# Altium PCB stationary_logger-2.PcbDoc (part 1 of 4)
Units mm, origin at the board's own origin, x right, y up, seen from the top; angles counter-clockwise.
Board outline 105 x 45 mm, 4 copper layers (Top Layer, Layer 2, Layer 3, Bottom Layer), stack 1.492 mm thick; 317 components, 187 nets, 816 pads, 302 vias.
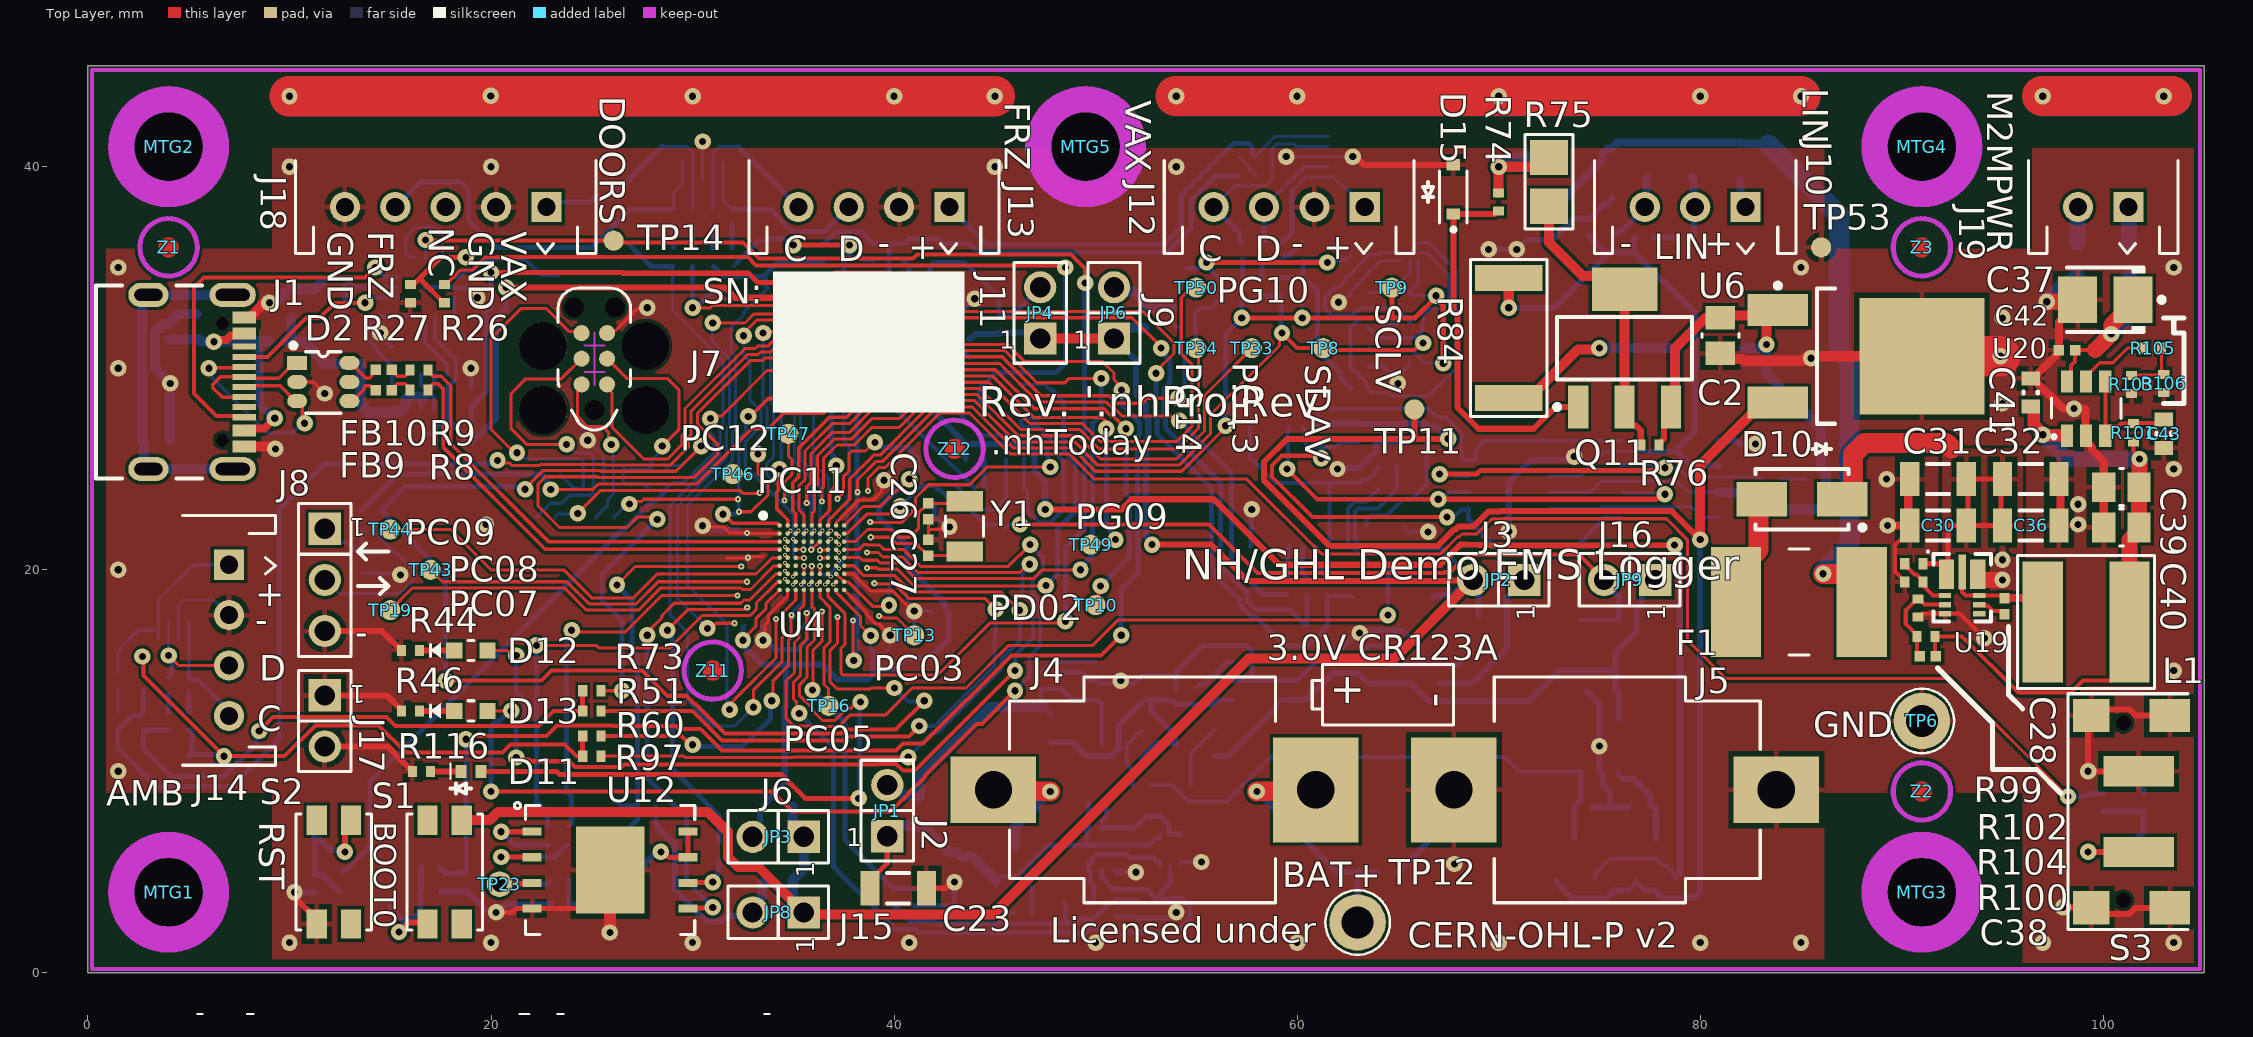
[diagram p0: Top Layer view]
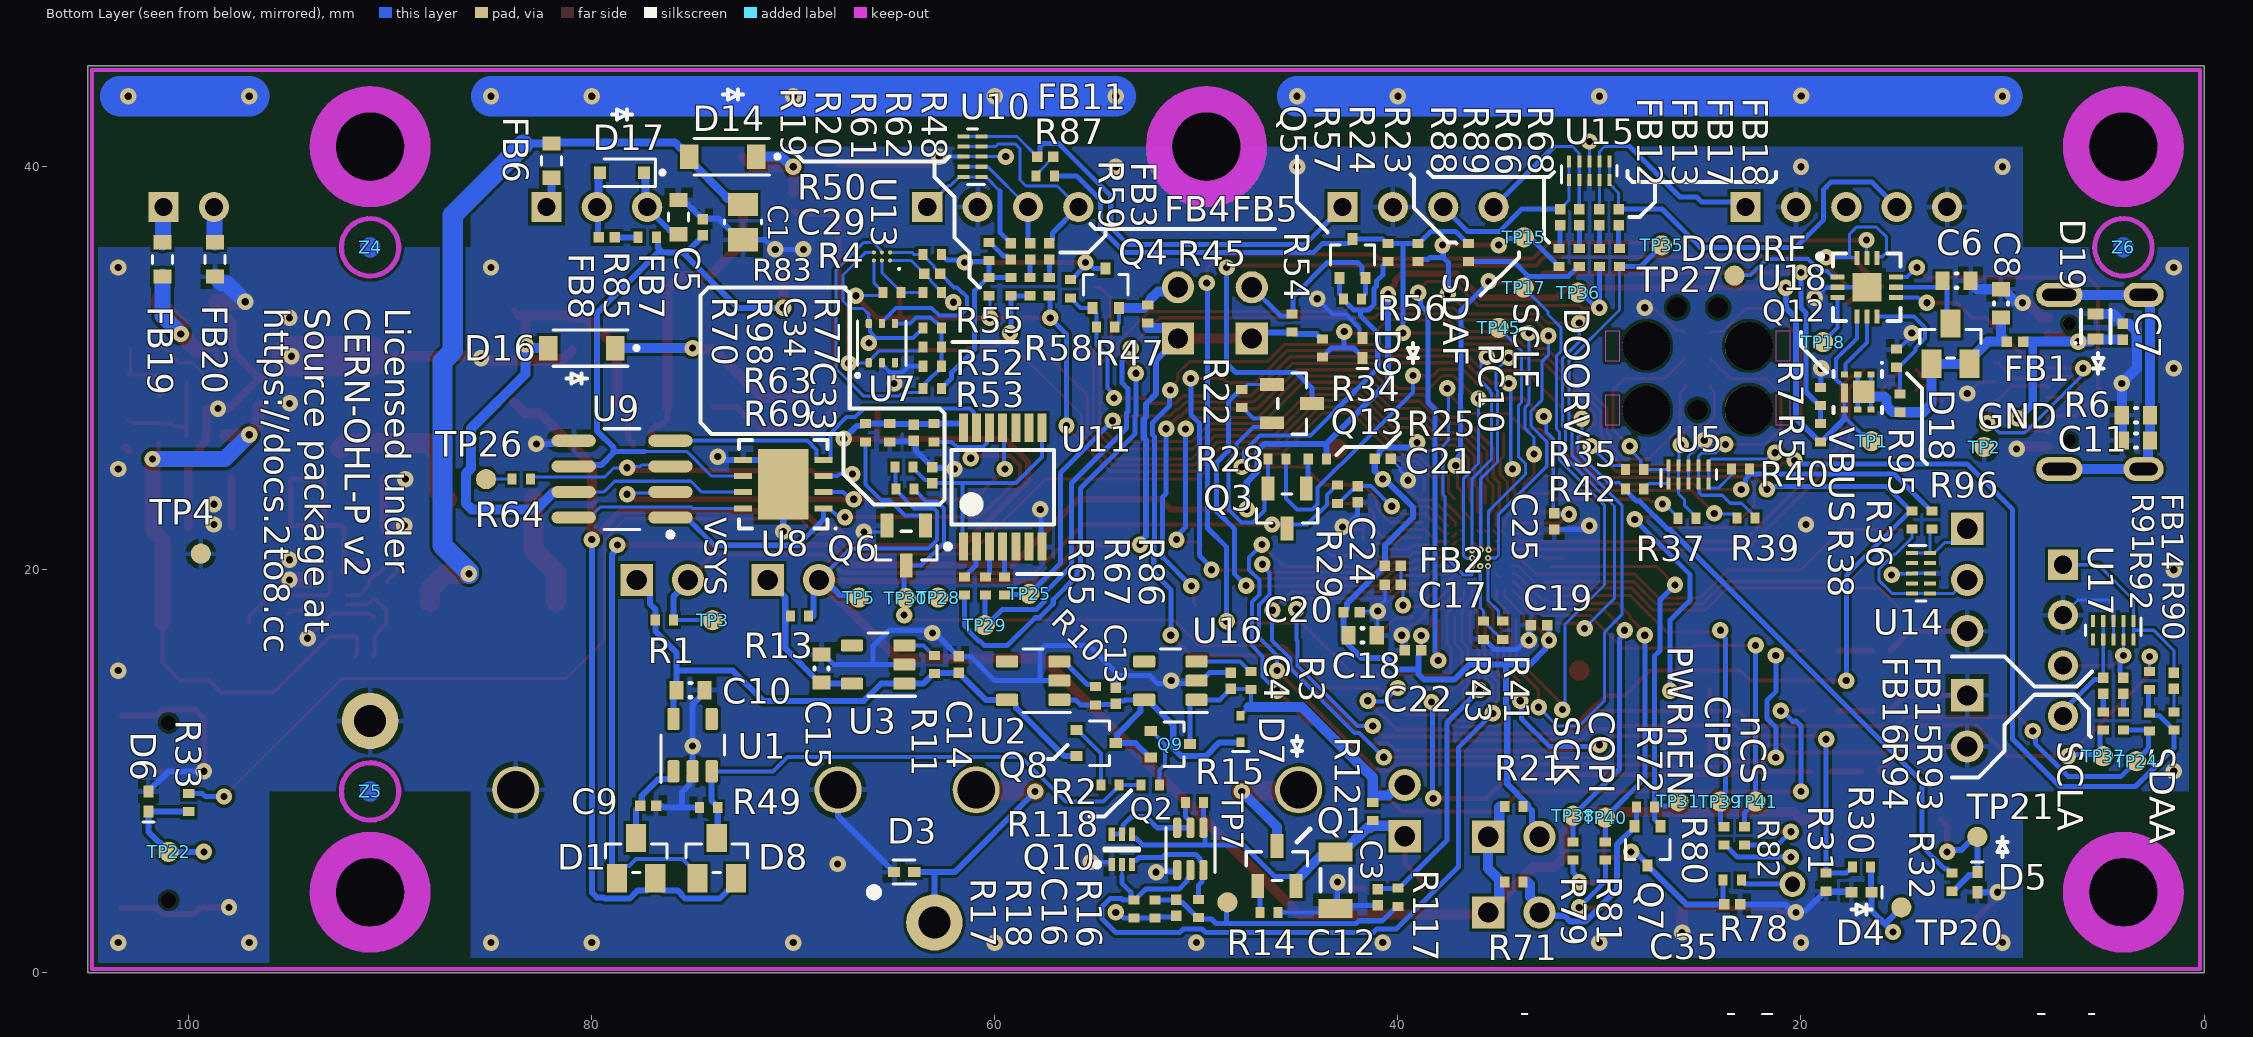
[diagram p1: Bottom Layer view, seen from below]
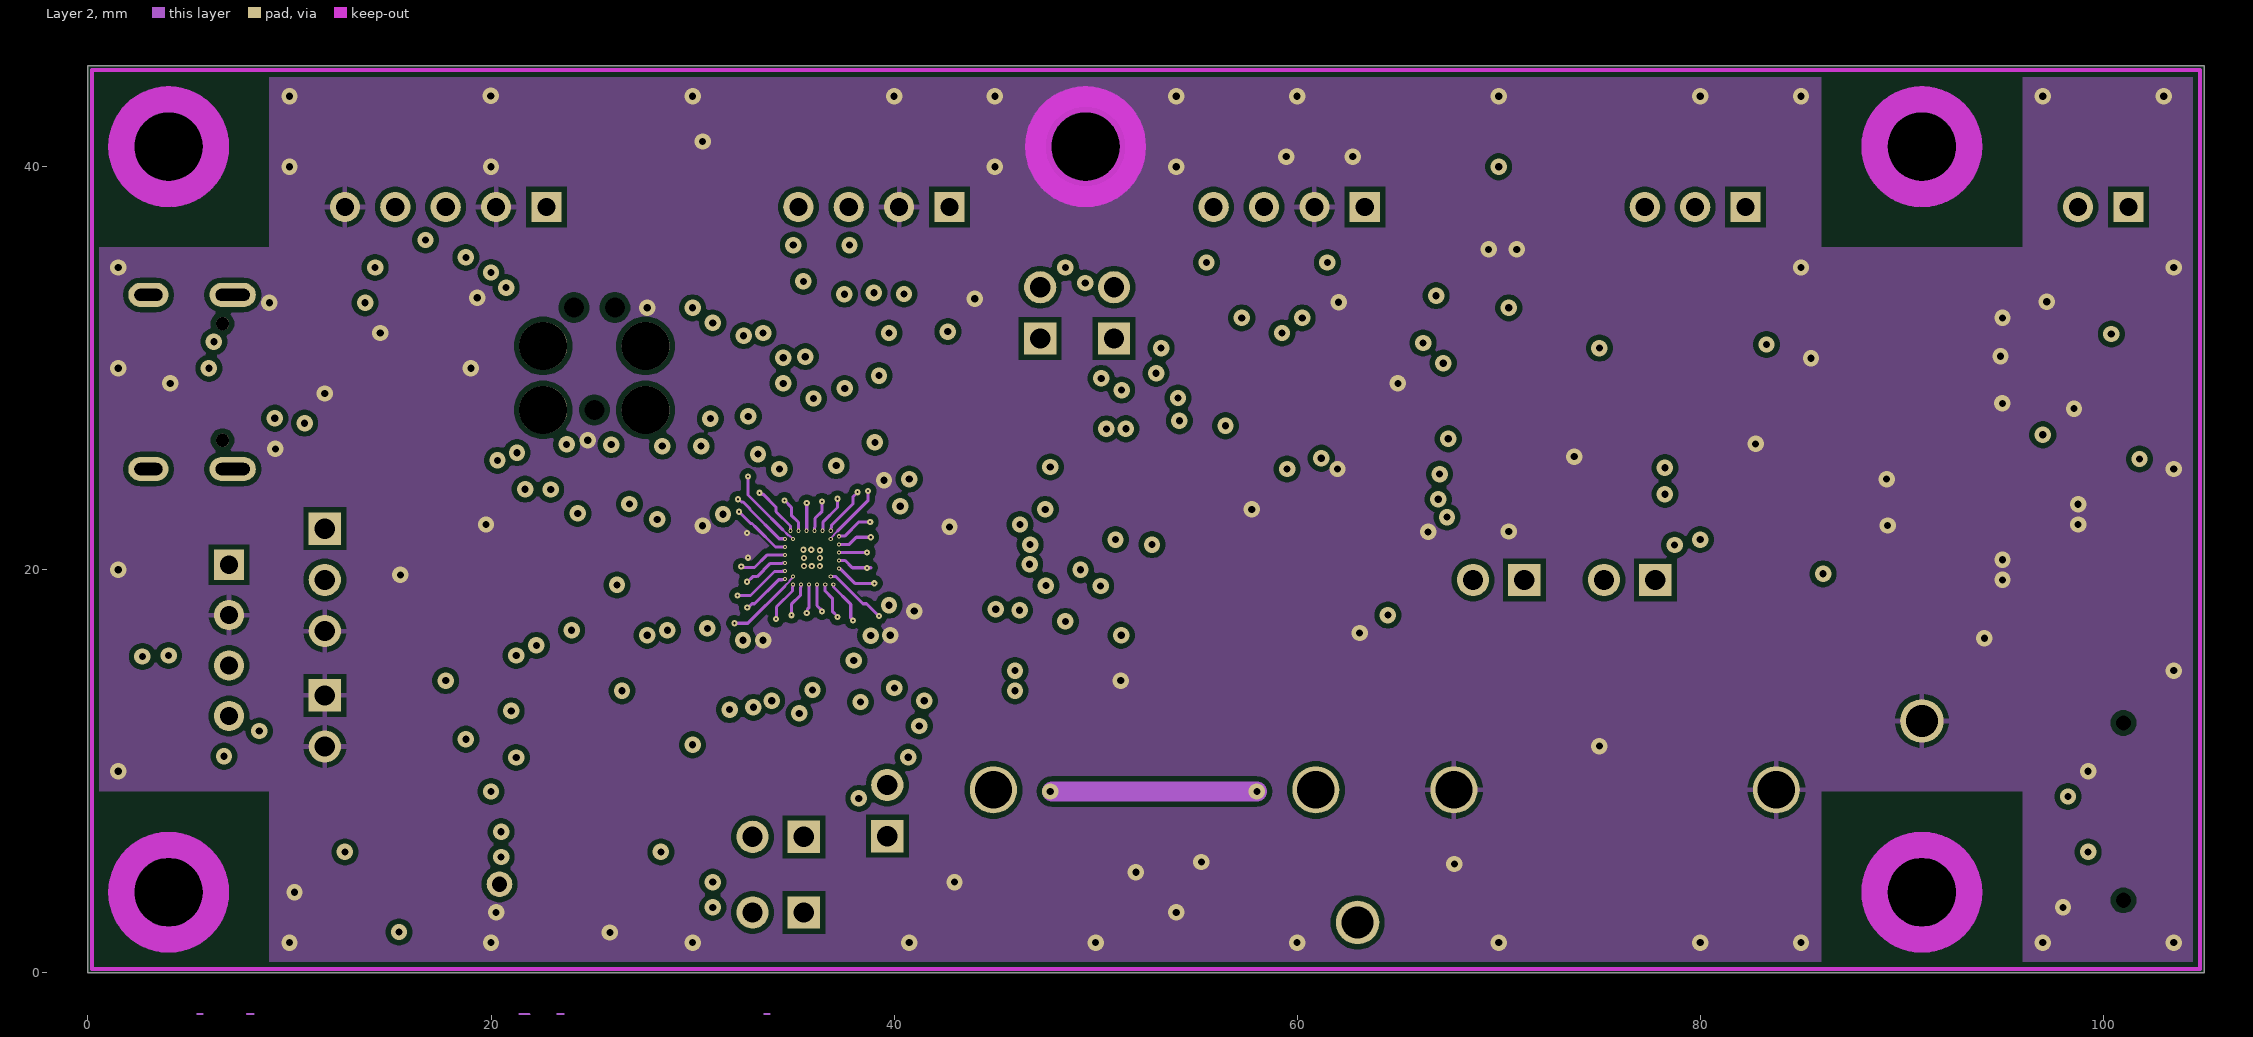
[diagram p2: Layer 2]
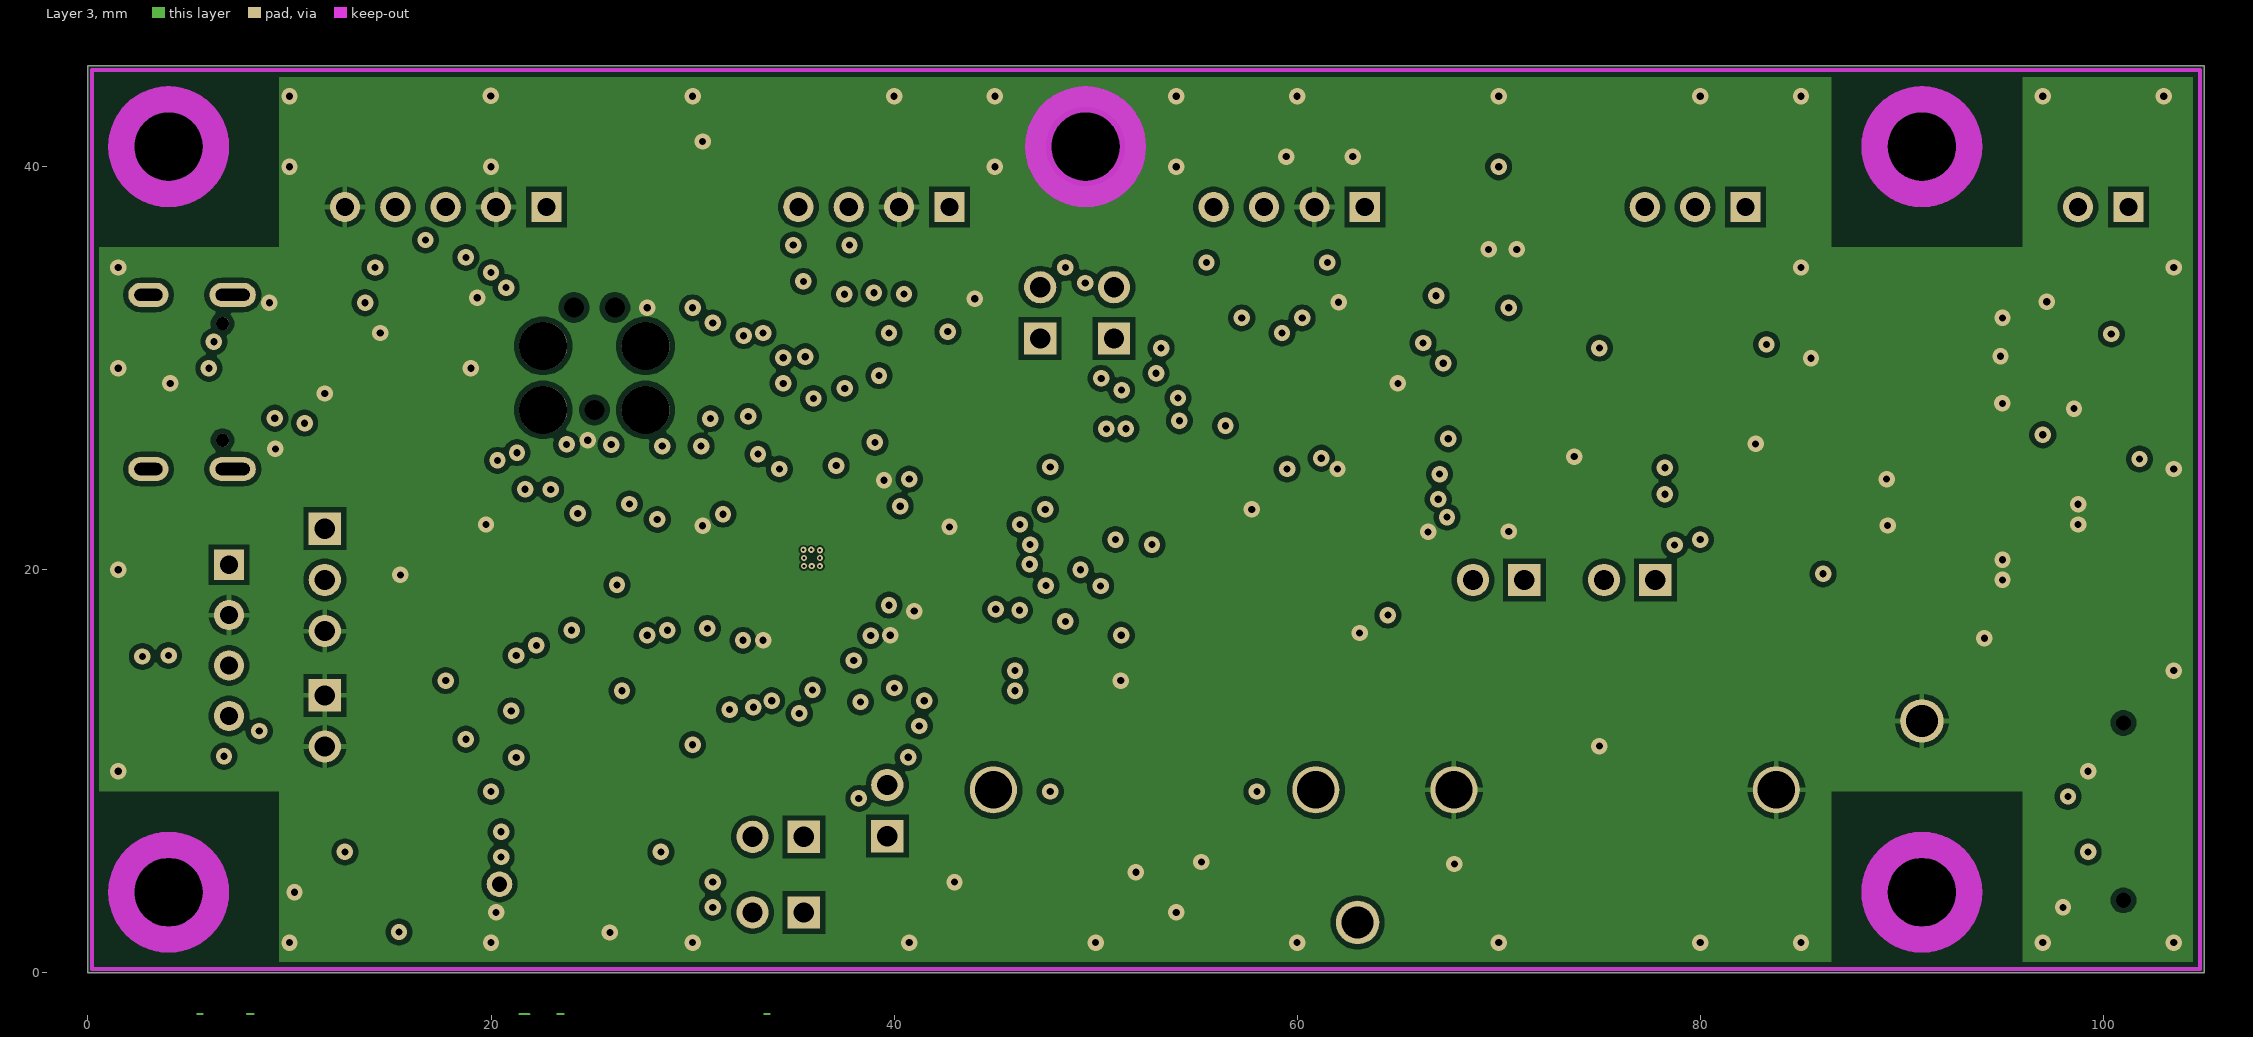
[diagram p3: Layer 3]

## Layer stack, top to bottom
Top Solder: solder mask 0.0356, Solder Resist, Dk 3.9
Top Layer: signal copper 0.0178
Dielectric 2: prepreg 0.0965, PP-006, Dk 3.9
Layer 2: signal copper 0.035
Dielectric 1: dielectric 1.1938, FR-4, Dk 3.9
Layer 3: signal copper 0.035
Dielectric 3: prepreg 0.0965, PP-006, Dk 3.9
Bottom Layer: signal copper 0.0178
Bottom Solder: solder mask 0.0356, Solder Resist, Dk 3.9

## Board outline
0,0 105,0 105,45 0,45

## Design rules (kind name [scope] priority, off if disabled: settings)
BoardOutlineClearance [All] p1: gap=0.254 ignorepadtopadclearanceinfootprint=FALSE except(0: Arc-SplitContinuation Track-SplitContinuation SMDPad-SplitContinuation THPad-SplitContinuation Via-SplitContinuation Fill-SplitContinuation Poly-SplitContinuation Region-SplitContinuation Text-SplitContinuation)
Clearance Clearance_Fanout [WithinRoom('FanoutRoom')] p1: gap=0.083 ignorepadtopadclearanceinfootprint=FALSE
Clearance Clearance_Inner [(OnLayer('Layer 2') OR OnLayer('Layer 3'))] p2: gap=0.254 ignorepadtopadclearanceinfootprint=FALSE
Clearance Clearance_Diff [(InDifferentialPairClass('All Differential Pairs'))] p3: gap=0.178 ignorepadtopadclearanceinfootprint=FALSE
Clearance [All] p4: gap=0.15 ignorepadtopadclearanceinfootprint=FALSE
ComponentClearance [All] p1: gap=0.1 collisioncheckmode=3 verticalgap=0.254 showdistances=FALSE
DiffPairsRouting [All] p1: maxlimit=0.203 minlimit=0.127 mostfreqgap=0.203 toplayer_mingap=0.203 toplayer_minwidth=0.178 toplayer_maxwidth=0.178 toplayer_prefwidth=0.178 midlayer1_maxgap=0.127 midlayer1_prefgap=0.127 midlayer1_minwidth=0.079 midlayer1_maxwidth=0.079 midlayer1_prefwidth=0.079 midlayer2_maxgap=0.127 midlayer2_prefgap=0.127 midlayer2_minwidth=0.079 midlayer2_maxwidth=0.079 midlayer2_prefwidth=0.079 bottomlayer_mingap=0.203 bottomlayer_minwidth=0.178 bottomlayer_maxwidth=0.178 bottomlayer_prefwidth=0.178 impedanceprofiledriven=TRUE impedanceprofileid={696D8CDD-15F8-4D84-82CF-D98015F80A4A} impedanceprofilevalue=90.000000 maxuncoupledlength=12.7
HoleSize HoleSize_microvia [IsMicroVia] p1: absolutevalues=TRUE maxlimit=0.3 minlimit=0.101 maxpercent=80.000 minpercent=20.000
HoleSize HoleSize_fanout [WithinRoom('FanoutRoom')] p2: absolutevalues=TRUE maxlimit=2 minlimit=0.12 maxpercent=80.000 minpercent=20.000
HoleSize [All] p3: absolutevalues=TRUE maxlimit=6.35 minlimit=0.152 maxpercent=80.000 minpercent=20.000
MatchedLengths DiffMatchedLengths [InDifferentialPair('No Differential Pair')] p1: tolerance=1.092 checknetsindiffpair=TRUE checkdiffpairvsdiffpair=FALSE checkxsignals=FALSE checkothers=FALSE
MinimumAnnularRing MinimumAnnularRing_MicroFanout [IsMicroVia AND WithinRoom('FanoutRoom')] p1: minimumring=0.05
MinimumAnnularRing MinimumAnnularRing_Fanout [WithinRoom('FanoutRoom')] p2: minimumring=0.087
MinimumAnnularRing MinimumAnnularRing_MicroVia [IsMicroVia] p3: minimumring=0.101
MinimumAnnularRing MinimumAnnularRing_Inner [(OnLayer('Layer 2') OR OnLayer('Layer 3'))] p4: minimumring=0.229
MinimumAnnularRing [All] p5: minimumring=0.203
MinimumSolderMaskSliver [All] p1: minsoldermaskwidth=0.102
PlaneClearance [All] p1: clearance=0.254
PolygonConnect [All] p1: thpad.connectstyle=Relief thpad.reliefconductorwidth=0.254 thpad.reliefentries=4 thpad.polygonreliefangle="90 Angle" thpad.airgapwidth=0.254 smdpad.connectstyle=Relief smdpad.reliefconductorwidth=0.254 smdpad.reliefentries=4 smdpad.polygonreliefangle="90 Angle" smdpad.airgapwidth=0.254 via.connectstyle=Direct via.reliefconductorwidth=0.254 via.reliefentries=4 via.polygonreliefangle="90 Angle" via.airgapwidth=0.254
RoomDefinition FanoutRoom [InComponentClass('FanoutClass')] p1: confinementstyle=ConfineIn formatcopy=TRUE lockcomponents=FALSE outline 33.159,18.314 38.5,18.314 38.5,23.14 33.159,23.14
RoutingVias RoutingMicroVias [IsMicroVia] p1: holewidth=0.102 width=0.203 viastyle="Through Hole" minholewidth=0.102 minwidth=0.203 maxholewidth=0.102 maxwidth=0.305
RoutingVias RoutingVias_Fanout [WithinRoom('FanoutRoom')] p2: holewidth=0.711 width=1.27 viastyle="Through Hole" minholewidth=0.13 minwidth=0.305 maxholewidth=0.711 maxwidth=1.27
RoutingVias [All] p3: holewidth=0.356 width=0.813 viastyle="Through Hole" minholewidth=0.356 minwidth=0.813 maxholewidth=0.711 maxwidth=1.27
SilkToSilkClearance [All] p1: silktosilkclearance=0.127
SilkToSolderMaskClearance [IsPad] p1: minsilkscreentomaskgap=0.127 clearancetoexposedcopper=TRUE
SolderMaskExpansion [All] p1: expansion=0.049 istentingtop=FALSE
Width Width_Fanout [WithinRoom('FanoutRoom')] p1: maxlimit=2.54 minlimit=0.102 preferedwidth=0.254
Width [All] p2: maxlimit=6.35 minlimit=0.152 preferedwidth=0.254
23 further rules are at their usual default settings.

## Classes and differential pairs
component class FanoutClass: U4
differential pair USB_ESD_D: +USB_ESD_D_P -USB_ESD_D_N
differential pair USB_CONN_D: +USB_CONN_D_P -USB_CONN_D_N
differential pair USB.D: +USB.D_P -USB.D_N
differential pair D: +D_P -D_N

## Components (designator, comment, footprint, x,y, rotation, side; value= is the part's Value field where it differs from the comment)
C1 "50V X7R 0805" CAPC2012X145 72.5,37.25 r270 bottom value=1E-6
C2 "50V X7R 0805" CAPC2012X145 81,31.625 r270 top value=1E-6
C3 "10V X7S 0402" CAPC1005X55,0402,L 41,3.75 r90 bottom value=1E-6
C4 "10V X7R 0402" CAPC1005X55,0402,L 48.291,14.5 r270 bottom value=1E-7
C5 "50V C0G 0402" CAPC1005X55,0402,L 74.5,37 r90 bottom value=1E-10
C6 "50V X7R 0603" CAPC1608X100,0603,L 12.28,34.345 r180 bottom value=1E-7
C7 "50V X7R 0402" CAPC1005X60,0402,L 4.03,31.82 r270 bottom value=1E-8
C8 "16V X7R 0603" CAPC1608X100,0603,L 10.08,33.22 r270 bottom value=4.7E-6
C9 "10V X7S 0402" CAPC1005X55,0402,L 77.2,8.3 r0 bottom value=1E-6
C10 "10V X5R 0603" CAPC1608X100,0603,L 75.1,14.025 r180 bottom value=2.2E-6
C11 "50V X7R 0603" CAPC1608X100,0603,L 3.38,26.42 r0 bottom value=1E-7
C12 "10V 20% 1206" CAPC3216X190,1206,L 43.1,4.6 r90 bottom value=4.7E-5
C13 "10V X7R 0402" CAPC1005X55,0402,L 54,13.75 r270 bottom value=1E-7
C14 "10V X7S 0402" CAPC1005X55,0402,L 61.8,15.3 r270 bottom value=1E-6
C15 "10V X5R 0603" CAPC1608X100,0603,L 68.6,15.1 r90 bottom value=2.2E-6
C16 "10V X7R 0402" CAPC1005X55,0402,L 51,3.225 r90 bottom value=1E-7
C17 "10V X7R 0402" CAPC1005X55,0402,L 40.25,19.25 r0 bottom value=1E-7
C18 "16V X7R 0603" CAPC1608X100,0603,L 41.75,16.75 r0 bottom value=4.7E-6
C19 "10V X7R 0402" CAPC1005X55,0402,L 33,17.25 r180 bottom value=1E-7
C20 "10V X7R 0402" CAPC1005X55,0402,L 42.3,17.89 r0 bottom value=1E-7
C21 "10V X7R 0402" CAPC1005X55,0402,L 40.75,25.5 r0 bottom value=1E-7
C22 "10V X7R 0402" CAPC1005X55,0402,L 39.25,16 r180 bottom value=1E-7
C23 "10V 20% 1206" CAPC3216X190,1206,L 40.2,4.2 r180 top value=4.7E-5
C24 "10V X7R 0402" CAPC1005X55,0402,L 42,23.75 r90 bottom value=1E-7
C25 "10V X7R 0402" CAPC1005X55,0402,L 32.25,22.4 r90 bottom value=1E-7
C26 "50V C0G 0402" CAPC1005X60,0402,L 41.705,22.9 r90 top value=1.5E-11
C27 "50V C0G 0402" CAPC1005X60,0402,L 41.705,21.1 r270 top value=1.5E-11
C28 "10V X7R 0402" CAPC1005X55,0402,L 95.1,18.2 r270 top value=1E-7
C29 "10V X7R 0402" CAPC1005X55,0402,L 63.107,34.7 r180 bottom value=1E-7
C30 "50V X7R 1206" CAPC3216X190,1206,L 91.8,22.2 r0 top value=4.7E-6
C31 "50V X7R 1206" CAPC3216X190,1206,L 91.8,24.5 r0 top value=4.7E-6
C32 "50V X7R 1206" CAPC3216X190,1206,L 96.4,24.5 r180 top value=4.7E-6
C33 "10V X7R 0402" CAPC1005X55,0402,L 63.11,24.7 r270 bottom value=1E-7
C34 "10V X7R 0402" CAPC1005X55,0402,L 64.015,26.8 r90 bottom value=1E-7
C35 "10V X7R 0402" CAPC1005X55,0402,L 23.41,3.4 r0 bottom value=1E-7
C36 "50V X7R 1206" CAPC3216X190,1206,L 96.4,22.2 r180 top value=4.7E-6
C37 "6.3V B 20% 55mO" CAPMP3528X21N[SIZEB] 100.1,33.4 r180 top value=0.0001
C38 "50V C0G 0402" CAPC1005X55,0402,L 91.3,15.7 r180 top value=4.7E-11
C39 "16V X5R 0805" CAPC2012X145 100.9,24.1 r180 top value=2.2E-5
C40 "16V X5R 0805" CAPC2012X145 100.9,22.1 r180 top value=2.2E-5
C41 "50V X7R 0603" CAPC1608X100,0603,L 96.4,28.8 r270 top value=1E-7
C42 "10V X7R 0402" CAPC1005X55,0402,L 98.2,30.9 r0 top value=1E-7
C43 "16V X7R 0603" CAPC1608X100,0603,L 103,26.75 r90 top value=4.7E-6
D1 "BAT54C" SOT23-3B 77.8,5.691 r0 bottom
D2 "TVS" SOT23-6 11.675,29.32 r0 top
D3 "BiTVS 3.6Vw 6.3Vc" TI_2-X1SON 64.5,5 r180 bottom
D4 "TVS 3.6Vw 8.9Vc" TI_2-X1SON_DFN65P100X60-2L 17,4 r0 bottom
D5 "TVS 3.6Vw 8.9Vc" TI_2-X1SON_DFN65P100X60-2L 11.25,4.5 r270 bottom
D6 "TVS 3.6Vw 8.9Vc" TI_2-X1SON_DFN65P100X60-2L 102,8.5 r90 bottom
D7 "30V 200mA" SOD-523_130x90x70 47.8,12.1 r90 bottom
D8 "BAT54C" SOT23-3B 73.8,5.691 r0 bottom
D9 "TVS 3.6Vw 8.9Vc" TI_2-X1SON_DFN65P100X60-2L 41.75,31 r90 bottom
D10 "50V 1A" DO-214AC_DIODES 85.05,23.5 r180 top
D11 "RED" LEDC1005X04NRED,0402, 19,10 r0 top
D12 "GRN" LEDC1608X06NGRN,0603, 19,16 r0 top
D13 "YEL" LEDC1608X06NYEL,0603, 19,13 r0 top
D14 "1N4148" SOD-123 73.5,40.5 r0 bottom
D15 "27V 300mW" SOD-323 67.75,38.877 r90 top
D16 "1N4148" SOD-123 80.5,31 r0 bottom
D17 "PESD1LIN" NEXPERIA_SOD-323_PESD1LIN 78.5,39.7 r0 bottom
D18 "BAT54C" SOT23-3B 12.58,31.22 r0 bottom
D19 "22WVM" DFN105P160X60-2N 5.38,32.075 r90 bottom
F1 "33V 1.1A" FUSC7351X12N,2920, 84.9,18.4 r0 top
FB1 "95 mOhm 1.5A" FER1005X60,0402,L 9.38,31.32 r0 bottom value=220
FB2 "0.65 Ohm 200mA" FER1005X60,0402,L 40.25,20.2 r180 bottom value=600
FB3 "0.49 Ohm 350mA" FER1005X60,0402,L 59.2,35.797 r90 bottom value=1000
FB4 "0.49 Ohm 350mA" FER1005X60,0402,L 58.25,35.797 r90 bottom value=1000
FB5 "0.49 Ohm 350mA" FER1005X60,0402,L 57.3,35.797 r90 bottom value=1000
FB6 "220 Ohm 2A" FER1608X100,0603,L 82,40.3 r270 bottom value=220
FB7 "220 Ohm 2A" FER1608X100,0603,L 75.7,37.5 r270 bottom value=220
FB8 "0.49 Ohm 350mA" FER1005X60,0402,L 79.25,36.5 r0 bottom value=1000
FB9 "0.49 Ohm 350mA" FER1005X60,0402,L 14.68,28.92 r0 top value=1000
FB10 "0.49 Ohm 350mA" FER1005X60,0402,L 14.68,29.92 r0 top value=1000
FB11 "0.49 Ohm 350mA" FER1005X60,0402,L 57.5,40.5 r0 bottom value=1000
FB12 "0.49 Ohm 350mA" FER1005X60,0402,L 31.95,37.5 r90 bottom value=1000
FB13 "0.49 Ohm 350mA" FER1005X60,0402,L 31,37.5 r90 bottom value=1000
FB14 "0.49 Ohm 350mA" FER1005X60,0402,L 1.5,14.5 r90 bottom value=1000
FB15 "0.49 Ohm 350mA" FER1005X60,0402,L 4,14.25 r90 bottom value=1000
FB16 "0.49 Ohm 350mA" FER1005X60,0402,L 5,14.25 r90 bottom value=1000
FB17 "0.49 Ohm 350mA" FER1005X60,0402,L 30,37.5 r90 bottom value=1000
FB18 "0.49 Ohm 350mA" FER1005X60,0402,L 29.05,37.5 r90 bottom value=1000
FB19 "220 Ohm 2A" FER1608X100,0603,L 101.3,35.4 r90 bottom value=220
FB20 "220 Ohm 2A" FER1608X100,0603,L 98.7,35.4 r90 bottom value=220
J1 "USBC_16p_4mnt" GCT_USB4105 3,29.32 r270 top locked
J2 "1x2 0.1in" HDR_2PIN 39.662,8.05 r90 top
J3 "1x2 0.1in" HDR_2PIN 70,19.5 r180 top
J4 "17-19mm dia" KEYSTONE_254 52.929,9.08 r0 top locked
J5 "17-19mm dia" KEYSTONE_254 75.779,9.08 r180 top locked
J6 "1x2 0.1in" HDR_2PIN 34.25,6.75 r180 top
J7 "TC2030" TAG-TC2030-LEGS 25.127,30.473 r90 top
J8 "1x3 0.1in" HDR_3PIN 11.75,19.5 r270 top
J9 "1x2 0.1in" HDR_2PIN 50.912,32.75 r90 top
J10 "JST XH" JST_S3B-XH-A(LF)(SN)_LESS_SILK 79.75,38 r180 top locked
J11 "1x2 0.1in" HDR_2PIN 47.25,32.75 r90 top
J12 "JST XH" JST_S4B-XH-A(LF)(SN)_LESS_SILK 59.607,38 r180 top locked
J13 "JST XH" JST_S4B-XH-A(LF)(SN)_LESS_SILK 39,38 r180 top locked
J14 "JST XH" JST_S4B-XH-A(LF)(SN)_LESS_SILK 7,16.5 r270 top locked
J15 "1x2 0.1in" HDR_2PIN 34.25,3 r180 top
J16 "1x2 0.1in" HDR_2PIN 76.5,19.5 r180 top
J17 "1x2 0.1in" HDR_2PIN 11.75,12.5 r270 top
J18 "JST XH" JST_S5B-XH-A(LF)(SN)_LESS_SILK 17.75,38 r180 top locked
J19 "JST XH" JST_S2B-XH-A(LF)(SN)_LESS_SILK 100,38 r180 top
JP1 "jumper" SULLINS_QPC02SXGN-RC 39.662,8.05 r90 top
JP2 "jumper" SULLINS_QPC02SXGN-RC 70,19.5 r0 top
JP3 "jumper" SULLINS_QPC02SXGN-RC 34.25,6.75 r0 top
JP4 "jumper" SULLINS_QPC02SXGN-RC 47.25,32.75 r90 top
JP6 "jumper" SULLINS_QPC02SXGN-RC 50.912,32.75 r270 top
JP8 "jumper" SULLINS_QPC02SXGN-RC 34.25,3 r0 top
JP9 "jumper" SULLINS_QPC02SXGN-RC 76.5,19.5 r0 top
L1 "3A 31mOhm" INDUCTOR-BOURNS_SRN6045 99.15,17.4 r0 top value=6.8E-6
MTG1 "mounting hole" MOUNT_HOLE_3MM_NOCOPPER 4,4 r0 top locked
MTG2 "mounting hole" MOUNT_HOLE_3MM_NOCOPPER 4,41 r0 top locked
MTG3 "mounting hole" MOUNT_HOLE_3MM_NOCOPPER 91,4 r0 top locked
MTG4 "mounting hole" MOUNT_HOLE_3MM_NOCOPPER 91,41 r0 top locked
MTG5 "mounting hole" MOUNT_HOLE_3MM_NOCOPPER 49.5,41 r0 top locked
Q1 "P-CH 30V 3.8A" SOT23-3#1 46,5.3 r180 bottom
Q2 "DUAL N/P 20V" SOT363 50.3,6.15 r90 bottom
Q3 "3904" SOT23-3#2 45.5,23.043 r270 bottom
Q4 "P-CH 20V 820mA" SOT323_65P200X125x100-GSD 54.5,33.972 r90 bottom
Q5 "P-CH 20V 820mA" SOT323_65P200X125x100-GSD 42.25,35.447 r90 bottom
Q6 "3904" SOT23-3#2 64.398,21.2 r270 bottom
Q7 "P-CH 20V 820mA" SOT323_65P200X125x100-GSD 27.61,6.3 r270 bottom
Q8 "P-CH 20V 820mA" SOT323_65P200X125x100-GSD 54.975,11.4 r180 bottom
Q9 "P-CH 20V 820mA" SOT323_65P200X125x100-GSD 51.291,11.346 r180 bottom
Q10 "DUAL N/P 20V" VISHAY_SOT563F_SOTFL50P160X60-6N 53.7,6.13 r90 bottom
Q11 "N-CH 55V 3.8A" SOT230P700X180-4N_ALPHA 76.25,31 r90 top
Q12 "N-CH 30V" STM_PWRFLAT_SON65P200X80_HS-8N 17.182,28.82 r270 bottom
Q13 "P-CH 30V 3.8A" SOT23-3#1 45.25,28.25 r270 bottom
R1 "1/16W 0402 Jumper" RESC1005X40,0402,L 76.4,17.5 r180 bottom value=0
R2 "1/16W 0402 1%" RESC1005X40,0402,L 54.291,9.316 r180 bottom value=300000
R3 "1/16W 0402 Jumper" RESC1005X40,0402,L 47.291,14.5 r90 bottom value=0
R4 "1/16W 0402 Jumper" RESC1005X40,0402,L 63.107,33.75 r180 bottom value=0
R5 "1/16W 0402 1%" RESC1005X40,0402,L 19.032,26.8 r270 bottom value=68000
R6 "1/10W 0603" RESC1608X60,0603,L 3.38,27.67 r0 bottom value=330
R7 "1/16W 0402 1%" RESC1005X40,0402,L 19.032,28.6 r270 bottom value=33000
R8 "1/16W 0402 Jumper" RESC1005X40,0402,L 16.43,28.92 r180 top value=0
R9 "1/16W 0402 Jumper" RESC1005X40,0402,L 16.43,29.92 r180 top value=0
R10 "1/16W 0402 Jumper" RESC1005X40,0402,L 55,13.75 r90 bottom value=0
R11 "1/16W 0402 Jumper" RESC1005X40,0402,L 63,15.3 r90 bottom value=0
R12 "1/16W 0402 Jumper" RESC1005X40,0402,L 41.25,8 r90 bottom value=0
R13 "1/16W 0402 Jumper" RESC1005X40,0402,L 69.7,17.7 r180 bottom value=0
R14 "1/16W 0402 1%" RESC1005X40,0402,L 46.4,3 r180 bottom value=1000
R15 "1/16W 0402 1%" RESC1005X40,0402,L 50.1,8.45 r0 bottom value=100000
R16 "1/16W 0402 1%" RESC1005X40,0402,L 49.9,3.2 r270 bottom value=8200
R17 "1/16W 0402 1%" RESC1005X40,0402,L 53.1,3.174 r270 bottom value=100000
R18 "1/16W 0402 1%" RESC1005X40,0402,L 52.05,3.174 r270 bottom value=10000
R19 "1/16W 0402 1%" RESC1005X40,0402,L 60.3,34.047 r270 bottom value=2740
R20 "1/16W 0402 1%" RESC1005X40,0402,L 59.2,34.047 r270 bottom value=2740
R21 "1/16W 0402 Jumper" RESC1005X40,0402,L 34.25,8.25 r180 bottom value=0
R22 "1/16W 0402 1%" RESC1005X40,0402,L 47.75,28.5 r90 bottom value=100000
R23 "1/16W 0402 1%" RESC1005X40,0402,L 36.5,35.75 r270 bottom value=4750
R24 "1/16W 0402 1%" RESC1005X40,0402,L 39,35.75 r270 bottom value=4750
R25 "1/16W 0402 1%" RESC1005X40,0402,L 44,25.5 r0 bottom value=1000
R26 "1/16W 0402 Jumper" RESC1005X40,0402,L 17.7,33.7 r90 top value=0
R27 "1/16W 0402 Jumper" RESC1005X40,0402,L 16,33.7 r90 top value=0
R28 "1/16W 0402 Jumper" RESC1005X40,0402,L 46,25.5 r0 bottom value=0
R29 "1/16W 0402 Jumper" RESC1005X40,0402,L 43,23.75 r90 bottom value=0
R30 "1/16W 0402 1%" RESC1005X40,0402,L 17,5.25 r180 bottom value=1000
R31 "1/16W 0402 1%" RESC1005X40,0402,L 18.75,4.5 r270 bottom value=100000
R32 "1/16W 0402 1%" RESC1005X40,0402,L 12.5,4.5 r270 bottom value=1000
R33 "1/16W 0402 1%" RESC1005X40,0402,L 100,8.45 r270 bottom value=1000
R34 "1/16W 0402 Jumper" RESC1005X40,0402,L 43.75,31 r270 bottom value=0
R35 "1/16W 0402 1%" RESC1005X40,0402,L 28.25,24.972 r0 bottom value=47.5
R36 "1/16W 0402 1%" RESC1005X40,0402,L 13.5,22.478 r90 bottom value=47.5
R37 "1/16W 0402 1%" RESC1005X40,0402,L 25.652,22.56 r0 bottom value=47.5
R38 "1/16W 0402 1%" RESC1005X40,0402,L 14.5,22.478 r90 bottom value=47.5
R39 "1/16W 0402 1%" RESC1005X40,0402,L 22.725,22.575 r0 bottom value=47.5
R40 "1/16W 0402 1%" RESC1005X40,0402,L 23,25 r180 bottom value=47.5
R41 "1/16W 0402 1%" RESC1005X40,0402,L 34.8,17 r270 bottom value=10000
R42 "1/16W 0402 1%" RESC1005X40,0402,L 28.25,24 r180 bottom value=47.5
R43 "1/16W 0402 1%" RESC1005X40,0402,L 35.75,17 r270 bottom value=402
R44 "1/16W 0402 1%" RESC1005X40,0402,L 16,16 r0 top value=100
R45 "1/16W 0402 Jumper" RESC1005X40,0402,L 52.412,32.697 r90 bottom value=0
R46 "1/16W 0402 1%" RESC1005X40,0402,L 16,13 r0 top value=100
R47 "1/16W 0402 1%" RESC1005X40,0402,L 54.5,32.046 r0 bottom value=1000000
R48 "1/16W 0402 Jumper" RESC1005X40,0402,L 56.25,33.947 r270 bottom value=0
R49 "1/16W 0402 1%" RESC1005X40,0402,L 74.2,8.2 r0 bottom value=100000
R50 "1/16W 0402 1%" RESC1005X40,0402,L 63.107,35.651 r0 bottom value=100
R51 "1/16W 0402 Jumper" RESC1005X40,0402,L 25,13 r180 top value=0
R52 "1/16W 0402 Jumper" RESC1005X40,0402,L 63.107,30.1 r0 bottom value=0
R53 "1/16W 0402 Jumper" RESC1005X40,0402,L 63.107,29 r180 bottom value=0
R54 "1/16W 0402 Jumper" RESC1005X40,0402,L 45.25,32.25 r90 bottom value=0
R55 "1/16W 0402 Jumper" RESC1005X40,0402,L 63.107,32.001 r0 bottom value=0
R56 "1/16W 0402 1%" RESC1005X40,0402,L 42.25,33.447 r0 bottom value=1000000
R57 "1/16W 0402 Jumper" RESC1005X40,0402,L 40.5,35.75 r270 bottom value=0
R58 "1/16W 0402 Jumper" RESC1005X40,0402,L 63.107,31.05 r0 bottom value=0
R59 "1/16W 0402 1%" RESC1005X40,0402,L 60.3,35.797 r90 bottom value=47.5
R60 "1/16W 0402 Jumper" RESC1005X40,0402,L 25,11.75 r180 top value=0
R61 "1/16W 0402 1%" RESC1005X40,0402,L 58.25,34.047 r90 bottom value=47.5
R62 "1/16W 0402 1%" RESC1005X40,0402,L 57.3,34.047 r90 bottom value=47.5
R63 "1/16W 0402 Jumper" RESC1005X40,0402,L 64.515,25.1 r0 bottom value=0
R64 "1/16W 0402 1%" RESC1005X40,0402,L 83.5,24.5 r0 bottom value=33000
R65 "1/16W 0402 Jumper" RESC1005X40,0402,L 61.515,19.2 r270 bottom value=0
R66 "1/16W 0402 1%" RESC1005X40,0402,L 30,35.5 r90 bottom value=47.5
R67 "1/16W 0402 Jumper" RESC1005X40,0402,L 60.465,19.2 r270 bottom value=0
R68 "1/16W 0402 1%" RESC1005X40,0402,L 29,35.5 r90 bottom value=47.5
R69 "1/16W 0402 1%" RESC1005X40,0402,L 64.465,24 r180 bottom value=100000
R70 "1/16W 0402 1%" RESC1005X40,0402,L 66.419,26.8 r90 bottom value=10000
R71 "1/16W 0402 Jumper" RESC1005X40,0402,L 34.25,4.5 r180 bottom value=0
R72 "1/16W 0402 1%" RESC1005X40,0402,L 27.71,8.225 r180 bottom value=1000000
R73 "1/16W 0402 Jumper" RESC1005X40,0402,L 25,14 r180 top value=0
R74 "1/16W 0402 1%" RESC1005X40,0402,L 70,38.25 r270 top value=100000
R75 "2.5W FUSE" RESC3216X70[1206] 72.5,39.25 r90 top value=10
R76 "1/16W 0402 Jumper" RESC1005X40,0402,L 77.5,26.2 r0 top value=0
R77 "1/16W 0402 1%" RESC1005X40,0402,L 63.015,26.8 r270 bottom value=4750
R78 "1/16W 0402 1%" RESC1005X40,0402,L 23.41,4.6 r0 bottom value=1000000
R79 "1/16W 0402 1%" RESC1005X40,0402,L 31.31,6.05 r270 bottom value=33
R80 "1/16W 0402 1%" RESC1005X40,0402,L 23.81,6.8 r270 bottom value=33
R81 "1/16W 0402 1%" RESC1005X40,0402,L 29.71,6.05 r270 bottom value=33
R82 "1/16W 0402 Jumper" RESC1005X40,0402,L 22.81,6.8 r90 bottom value=0
R83 "1/16W 0402 Jumper" RESC1005X40,0402,L 65.107,33.75 r180 bottom value=0
R84 "1W 2512 1%" RESC6534X70[2512] 70.5,31.5 r90 top value=1000
R85 "1/16W 0402 Jumper" RESC1005X40,0402,L 77.25,36.5 r180 bottom value=0
R86 "1/16W 0402 Jumper" RESC1005X40,0402,L 59.515,19.2 r270 bottom value=0
R87 "1/16W 0402 1%" RESC1005X40,0402,L 57.5,39.55 r0 bottom value=47.5
R88 "1/16W 0402 1%" RESC1005X40,0402,L 32,35.5 r90 bottom value=47.5
R89 "1/16W 0402 1%" RESC1005X40,0402,L 31,35.5 r90 bottom value=47.5
R90 "1/16W 0402 1%" RESC1005X40,0402,L 1.5,12.5 r90 bottom value=47.5
R91 "1/16W 0402 1%" RESC1005X40,0402,L 2.7,14.5 r90 bottom value=4750
R92 "1/16W 0402 1%" RESC1005X40,0402,L 2.702,12.448 r270 bottom value=4750
R93 "1/16W 0402 1%" RESC1005X40,0402,L 4,12.5 r90 bottom value=47.5
R94 "1/16W 0402 1%" RESC1005X40,0402,L 5,12.5 r90 bottom value=47.5
R95 "1/16W 0402 1%" RESC1005X40,0402,L 15.08,28.267 r270 bottom value=10000
R96 "1/16W 0402 1%" RESC1005X40,0402,L 15.25,30.5 r270 bottom value=2740
R97 "1/16W 0402 Jumper" RESC1005X40,0402,L 25,10.75 r180 top value=0
R98 "1/16W 0402 1%" RESC1005X40,0402,L 65.217,26.8 r270 bottom value=100000
R99 "1/16W 0402 1%" RESC1005X40,0402,L 90.6,20.3 r180 top value=100000
R100 "1/10W 0402 1%" RESC1005X40,0402,L 91.2,16.7 r180 top value=178000
R101 "1/16W 0402 1%" RESC1005X40,0402,L 101.5,26.8 r90 top value=1000000
R102 "1/10W 0402 1%" RESC1005X40,0402,L 90.6,19.4 r180 top value=23700
R103 "1/10W 0402 1%" RESC1005X40,0402,L 101.4,29.2 r270 top value=23700
R104 "1/16W 0402 1%" RESC1005X40,0402,L 90.8,18.1 r270 top value=33000
R105 "1/16W 0402 Jumper" RESC1005X40,0402,L 102.45,31 r0 top value=0
R106 "1/16W 0402 1%" RESC1005X40,0402,L 103,29.25 r270 top value=1000000
R116 "1/16W 0402 1%" RESC1005X40,0402,L 16.55,10 r0 top value=100
R117 "1/16W 0402 1%" RESC1005X40,0402,L 40,3.75 r270 bottom value=100
R118 "1/16W 0402 1%" RESC1005X40,0402,L 52.291,9.316 r0 bottom value=300000
S1 "SPST-NO" EVQP2x02W_MIRROR 17.7,5 r90 top
S2 "SPST-NO" EVQP2x02W_MIRROR 12.2,5 r270 top
S3 "SPST-NO" TE_1571300 101,8 r90 top
TP1 "TP SMD 1mm" "TP_SMD_Ø1.0mm NO SILK"#1 16.5,26.382 r90 bottom
TP2 "TP SMD 1mm" "TP_SMD_Ø1.0mm NO SILK"#1 10.907,26.093 r90 bottom
TP3 "TP SMD 1mm" "TP_SMD_Ø1.0mm NO SILK"#1 74,17.5 r90 bottom
TP4 "TP SMD 1mm" "TP_SMD_Ø1.0mm NO SILK"#1 99.4,20.8 r0 bottom
TP5 "TP SMD 1mm" "TP_SMD_Ø1.0mm NO SILK"#1 66.75,18.625 r90 bottom
TP6 "TP BLK" KEYSTONE_5011 91,12.5 r90 top
TP7 "TP SMD 1mm" "TP_SMD_Ø1.0mm NO SILK"#1 48.458,3.5 r90 bottom
TP8 "TP SMD 1mm" "TP_SMD_Ø1.0mm NO SILK"#2 61.3,31.2 r180 top
TP9 "TP SMD 1mm" "TP_SMD_Ø1.0mm NO SILK"#1 64.7,34 r180 top
TP10 "TP SMD 1mm" "TP_SMD_Ø1.0mm NO SILK"#1 50,18.25 r90 top
TP11 "TP SMD 1mm" "TP_SMD_Ø1.0mm NO SILK"#1 65.818,27.956 r180 top
TP12 "TP BLK" KEYSTONE_5011 63,2.5 r0 top
TP13 "TP SMD 1mm" "TP_SMD_Ø1.0mm NO SILK"#1 41,16.75 r90 top
TP14 "TP SMD 1mm" "TP_SMD_Ø1.0mm NO SILK"#1 26.084,36.331 r90 top
TP15 "TP SMD 1mm" "TP_SMD_Ø1.0mm NO SILK"#1 33.75,36.5 r0 bottom
TP16 "TP SMD 1mm" "TP_SMD_Ø1.0mm NO SILK"#1 36.75,13.25 r90 top
TP17 "TP SMD 1mm" "TP_SMD_Ø1.0mm NO SILK"#1 33.75,34 r0 bottom
TP18 "TP SMD 1mm" "TP_SMD_Ø1.0mm NO SILK"#1 18.9,31.3 r90 bottom
TP19 "TP SMD 1mm" "TP_SMD_Ø1.0mm NO SILK"#1 15,18 r90 top
TP20 "TP SMD 1mm" "TP_SMD_Ø1.0mm NO SILK"#1 15.017,3.25 r90 bottom
TP21 "TP SMD 1mm" "TP_SMD_Ø1.0mm NO SILK"#1 11.25,6.75 r90 bottom
TP22 "TP SMD 1mm" "TP_SMD_Ø1.0mm NO SILK"#1 101,6 r90 bottom
TP23 "TP TH  0.78mm" TP_TH078H127P 20.42,4.4 r90 top
TP24 "TP SMD 1mm" "TP_SMD_Ø1.0mm NO SILK"#1 3.358,10.502 r90 bottom
TP25 "TP SMD 1mm" "TP_SMD_Ø1.0mm NO SILK"#1 58.282,18.8 r0 bottom
TP26 "TP SMD 1mm" "TP_SMD_Ø1.0mm NO SILK"#1 85.25,24.5 r0 bottom
TP27 "TP SMD 1mm" "TP_SMD_Ø1.0mm NO SILK"#1 23.3,34.6 r90 bottom
TP28 "TP SMD 1mm" "TP_SMD_Ø1.0mm NO SILK"#1 62.815,18.625 r0 bottom
TP29 "TP SMD 1mm" "TP_SMD_Ø1.0mm NO SILK"#1 60.5,17.25 r0 bottom
TP30 "TP SMD 1mm" "TP_SMD_Ø1.0mm NO SILK"#1 64.415,18.6 r0 bottom
TP31 "TP SMD 1mm" "TP_SMD_Ø1.0mm NO SILK"#1 26.077,8.508 r90 bottom
TP33 "TP SMD 1mm" "TP_SMD_Ø1.0mm NO SILK"#1 57.75,31 r90 top
TP34 "TP SMD 1mm" "TP_SMD_Ø1.0mm NO SILK"#1 55,31 r90 top
TP35 "TP SMD 1mm" "TP_SMD_Ø1.0mm NO SILK"#1 26.9,36.1 r0 bottom
TP36 "TP SMD 1mm" "TP_SMD_Ø1.0mm NO SILK"#1 31.054,33.75 r0 bottom
TP37 "TP SMD 1mm" "TP_SMD_Ø1.0mm NO SILK"#1 5,10.75 r90 bottom
TP38 "TP SMD 1mm" "TP_SMD_Ø1.0mm NO SILK"#1 31.31,7.8 r90 bottom
TP39 "TP SMD 1mm" "TP_SMD_Ø1.0mm NO SILK"#1 24,8.5 r90 bottom
TP40 "TP SMD 1mm" "TP_SMD_Ø1.0mm NO SILK"#1 29.71,7.7 r90 bottom
TP41 "TP SMD 1mm" "TP_SMD_Ø1.0mm NO SILK"#1 22.25,8.5 r90 bottom
TP43 "TP SMD 1mm" "TP_SMD_Ø1.0mm NO SILK"#1 17,20 r90 top
TP44 "TP SMD 1mm" "TP_SMD_Ø1.0mm NO SILK"#1 15,22 r90 top
TP45 "TP SMD 1mm" "TP_SMD_Ø1.0mm NO SILK"#1 35,32 r90 bottom
TP46 "TP SMD 1mm" "TP_SMD_Ø1.0mm NO SILK"#1 32,24.75 r90 top
TP47 "TP SMD 1mm" "TP_SMD_Ø1.0mm NO SILK"#1 34.75,26.75 r90 top
TP49 "TP SMD 1mm" "TP_SMD_Ø1.0mm NO SILK"#1 49.75,21.25 r90 top
TP50 "TP SMD 1mm" "TP_SMD_Ø1.0mm NO SILK"#1 55,34 r90 top
TP53 "TP SMD 1mm" "TP_SMD_Ø1.0mm NO SILK"#1 86,36 r180 top
U1 "3.3V 200mA" TI_SOT-23-5_95P280X145L 75,11.3 r90 bottom
U2 "MAX40203" TI_SOT-23-5_95P280X145L 58.1,14.5 r0 bottom
U3 "1.8V 200mA" TI_SOT-23-5_95P280X145L 65.791,15.3 r0 bottom
U4 "STM32L476JEY6TR" STM_BGA72C40P9X9_441X376X58 35.92,20.6 r0 top locked
U5 "PUSB3FA1Z" NEXPERIA_DFN2510_50p250x100x50-10 25.577,24.722 r90 bottom
U6 "35V 5V 0.5A" ONSEMI_DPAK229P991X238-3N 88.25,30.598 r0 top
U7 "TMP117" TI-TMP117-WSON 65.607,31.25 r90 bottom
U8 "LIN XCV" SON80P400X100_HS-9N_NOVIA 70.5,24.25 r0 bottom
U9 "LIN XCV" SOIC127P600X170-8N 78.5,24.5 r0 bottom
U10 "PUSB3FA1Z" NEXPERIA_DFN2510_50p250x100x50-10 61.107,40.5 r0 bottom
U11 "Logic level translator" TSOP65P640X110-14N 59.61,24.1 r90 bottom
U12 "1Gb SPI" SON127P800X95_HS-9N_no_via 25.91,5.1 r0 top
U13 "AMS_AS621x" AMS_BGA6C40P3X2_150X102X60 65.607,35.55 r0 bottom
U14 "PUSB3FA1Z" NEXPERIA_DFN2510_50p250x100x50-10 14.048,19.828 r180 bottom
U15 "PUSB3FA1Z" NEXPERIA_DFN2510_50p250x100x50-10 30.5,39.8 r90 bottom
U16 "MAX40203" TI_SOT-23-5_95P280X145L 51.291,14.5 r0 bottom
U17 "PUSB3FA1Z" NEXPERIA_DFN2510_50p250x100x50-10 4.5,17 r270 bottom
U18 "STM_TCPP01-M12" QFN50P300X300X100_HS-13N 16.73,34.02 r180 bottom
U19 "DIO-AP6335x" DIO_VDFN3020-13A 93,19.1 r0 top
U20 "TI_TPS2553" SOT_23_6 99.15,28 r90 top
Y1 "20ppm 12.5pF" FC-135 43.5,22.15 r270 top value=32768
Z1 "NOBOM-00010" FIDUCIAL_1_3_KEEPOUT 4,36 r0 top locked
Z2 "NOBOM-00010" FIDUCIAL_1_3_KEEPOUT 91,9 r0 top locked
Z3 "NOBOM-00010" FIDUCIAL_1_3_KEEPOUT 91,36 r0 top locked
Z4 "NOBOM-00010" FIDUCIAL_1_3_KEEPOUT 91,36 r180 bottom locked
Z5 "NOBOM-00010" FIDUCIAL_1_3_KEEPOUT 91,9 r180 bottom locked
Z6 "NOBOM-00010" FIDUCIAL_1_3_KEEPOUT 4,36 r180 bottom locked
Z11 "NOBOM-00010" FIDUCIAL_1_3_KEEPOUT 31,15 r0 top locked
Z12 "NOBOM-00010" FIDUCIAL_1_3_KEEPOUT 43,26 r0 top locked

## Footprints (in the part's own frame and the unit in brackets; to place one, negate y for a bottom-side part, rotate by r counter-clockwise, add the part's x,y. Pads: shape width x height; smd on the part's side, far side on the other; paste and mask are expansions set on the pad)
AMS_BGA6C40P3X2_150X102X60 [mm] "BGA, 6-Leads, Body 1.50x1.02mmx0.60mm, Pitch 0.40mm"
  round 0.2 smd mask+0.049: A1(-0.4,0.2) A2(0,0.2) A3(0.4,0.2) B1(-0.4,-0.2) B2(0,-0.2) B3(0.4,-0.2)
  silkscreen extent -0.9,0.57 -0.8,0.67, body extent -0.75,-0.52 0.75,0.52, height 0.6
CAPC1005X55,0402,L [mm] "Chip Capacitor, Body 1.0x0.5mm, Height 0.55mm, IPC High Density"
  rect 0.52x0.52 smd: 1(-0.4,0) 2(0.4,0)
  body extent -0.55,-0.3 0.55,0.3, height 0.55
CAPC1005X60,0402,L [mm]
  rect 0.52x0.52 smd: 1(-0.4,0) 2(0.4,0)
  body extent -0.55,-0.3 0.55,0.3, height 0.6
CAPC1608X100,0603,L [mm] "Chip Capacitor, Body 1.6x0.8mm, Height 1.0mm, IPC High Density"
  rect 0.7x0.9 smd: 1(-0.7,0) 2(0.7,0)
  silkscreen extent -0.05,-0.35 0.05,0.35, body extent -0.87,-0.47 0.88,0.48, height 1
CAPC2012X145 [mm]
  rect 1.16x1.47 smd: 1(-0.875,0) 2(0.875,0)
  silkscreen extent -0.1,-0.92 0.1,0.92, body extent -1,-0.63 1,0.63, height 1.45
CAPC3216X190,1206,L [mm] "Chip Capacitor, Body 3.2x1.6mm, Height 1.9mm, IPC High Density"
  rect 0.95x1.7 smd: 1(-1.4,0) 2(1.4,0)
  silkscreen extent -0.55,-0.75 0.55,0.75, body extent -1.7,-0.9 1.7,0.9, height 1.9
CAPMP3528X21N[SIZEB] [mm] "Molded Capacitor, 2-Leads, Body 3.50x2.85mm, IPC Medium Density"
  rect 1.95x2.3 smd: +(-1.375,0) -(1.375,0)
  silkscreen extent -2.93,-1.6 1.9,1.6, body extent -1.9,-1.5 1.85,1.5, height 2.1
DFN105P160X60-2N [mm] "DFN, 2-Leads, Body 1.00x1.60mm, Pitch 1.05mm, IPC Medium Density"
  rect 0.55x0.8 smd: A(0.625,0) K(-0.625,0)
  silkscreen extent -0.87,-0.73 0.82,1.05, body extent -0.82,-0.53 0.82,0.53, height 0.61
DIO_VDFN3020-13A [mm] "SON, 9-Leads, Body 3.0x2.0mm, Pitch 0.45mm, IPC Medium Density"
  rect 0.75x1.47 smd: 1(-0.772,0.686) 8(0.772,0.686)
  rect 0.6x0.27 smd mask+0.039: 2(-0.847,-0.375) 3(-0.847,-0.825) 4(-0.847,-1.275) 5(0.847,-1.275) 6(0.847,-0.825) 7(0.847,-0.375)
  rect 0.39x1.73 smd: 9(0,0.79)
  silkscreen extent -1.75,-1.68 1.43,1.85, body extent -1,-1.5 1,1.5, height 0.86
DO-214AC_DIODES [mm] "Molded Diode, 2-Leads, Body 4.30x2.61mm, IPC Medium Density"
  rect 2.5x1.7 smd: A(2,0) K(-2,0)
  silkscreen extent -3.13,-1.5 2.3,1.52, body extent -2.3,-1.46 2.3,1.46, height 2.4
EVQP2x02W_MIRROR [mm] "Panasonic EQVP2 switch with 2.5mm nominal height"
  rect 1.45x1 smd: 1(-2.575,0.85) 2(-2.575,-0.85) 3(2.575,0.85) 4(2.575,-0.85)
  silkscreen extent -2.88,-1.88 2.88,1.88, body extent -2.75,-1.75 2.75,1.75, height 2.5
FC-135 [mm]
  rect 1x1.8 smd: 1(-1.25,0) 2(1.25,0)
  silkscreen extent -0.51,-0.95 0.51,0.94, body extent -1.6,-0.75 1.6,0.75, height 0.81
FER1005X60,0402,L [mm]
  rect 0.52x0.52 smd: 1(-0.4,0) 2(0.4,0)
  body extent -0.55,-0.3 0.55,0.3, height 0.6
FER1608X100,0603,L [mm]
  rect 0.71x0.91 smd: 1(-0.85,0) 2(0.85,0)
  silkscreen extent -0.2,-0.5 0.2,0.5, body extent -0.8,-0.4 0.8,0.4, height 1
FIDUCIAL_1_3_KEEPOUT [mm] "1mm dia fiducial with 3mm dia keepout"
  Top Layer circle w0.5: c0,0 r0.25
  Top Layer keep-out circle w0.254: c0,0 r1.425
FUSC7351X12N,2920, [mm] "Chip Fuse, 2-Leads, Body 7.36x5.12mm, IPC Medium Density"
  rect 2.5x5.45 smd: 1(-3.125,0) 2(3.125,0)
  silkscreen extent -0.5,-2.62 0.5,2.63, body extent -3.99,-2.72 3.99,2.72, height 1.25
GCT_USB4105 [mm] "USB-C receptacle 16 pins + 8 dummy"
  rect 0.6x1.15 smd: A1_B12(-3.2,4.755) A4_B9(-2.4,4.755) B1_A12(3.2,4.755) B4_A9(2.4,4.755)
  rect 0.3x1.15 smd: A5(-1.25,4.755) A6(-0.25,4.755) A7(0.25,4.755) A8(1.25,4.755) B5(1.75,4.755) B6(0.75,4.755) B7(-0.75,4.755) B8(-1.75,4.755)
  oval 1.2x2.3 hole 0.6 slot 1.7 at 90 deg: S1(-4.32,4.18) S4(4.32,4.18)
  oval 1.2x2 hole 0.6 slot 1.4 at 90 deg: S2(-4.32,0) S3(4.32,0)
  round 0.65 hole 0.65 unplated mask+0: ""(-2.89,3.68) ""(2.89,3.68)
  silkscreen extent -4.79,-2.6 4.79,2.65, body extent -4.79,-2.55 4.79,5.16, height 3.31
HDR_2PIN [mm]
  rect 1.6x1.6 hole 1 paste-2539.97 mask+0: 1(-1.27,0)
  round 1.6 hole 1 paste-2539.97 mask+0: 2(1.27,0)
  silkscreen extent -2.5,-1.3 2.5,1.3, body extent -2.54,-1.27 2.54,1.27, height 10.74
HDR_3PIN [mm] "3PIN SULLINS STRIP HEADER .100"
  rect 1.6x1.6 hole 1 paste-2539.97 mask+0: 1(-2.54,0)
  round 1.6 hole 1 paste-2539.97 mask+0: 2(0,0) 3(2.54,0)
  silkscreen extent -3.8,-1.3 3.8,1.3, body extent -3.81,-1.27 3.81,1.27, height 10.74
INDUCTOR-BOURNS_SRN6045 [mm] "SMT POWER INDUCTOR"
  rect 2x6 smd: 1(-2.15,0) 2(2.15,0)
  silkscreen extent -3.4,-3.3 3.4,3.3, body extent -3.01,-3.02 2.99,2.98, height 4.5
JST_S2B-XH-A(LF)(SN)_LESS_SILK [mm] "JST 2.5mm 2-pin right angle header"
  rect 1.5x1.5 hole 0.9: 1(-1.25,0)
  round 1.5 hole 0.9: 2(1.25,0)
  silkscreen extent -3.7,-2.3 3.7,2.3, body extent -3.7,-9.2 3.7,2.3, height 5.95
JST_S3B-XH-A(LF)(SN)_LESS_SILK [mm] "JST 2.5mm 3-pin right angle header"
  rect 1.5x1.5 hole 0.9: 1(-2.5,0)
  round 1.5 hole 0.9: 2(0,0) 3(2.5,0)
  silkscreen extent -5,-2.3 5,2.3, body extent -4.95,-9.2 4.95,2.3, height 6.15
JST_S4B-XH-A(LF)(SN)_LESS_SILK [mm] "JST 2.5mm 4-pin right angle header"
  rect 1.5x1.5 hole 0.9: 1(-3.75,0)
  round 1.5 hole 0.9: 2(-1.25,0) 3(1.25,0) 4(3.75,0)
  silkscreen extent -6.2,-2.3 6.2,2.3, body extent -6.2,-9.2 6.2,2.3, height 6.15
JST_S5B-XH-A(LF)(SN)_LESS_SILK [mm] "JST 2.5mm 5-pin right angle header"
  rect 1.5x1.5 hole 0.9: 1(-5,0)
  round 1.5 hole 0.9: 2(-2.5,0) 3(0,0) 4(2.5,0) 5(5,0)
  silkscreen extent -7.45,-2.3 7.45,2.3, body extent -7.4,-9.2 7.45,2.2, height 6.1
KEYSTONE_254 [mm]
  rect 4.24x3.3 / inner round 2.337 / far side round 2.337 hole 1.85: 1(-8,0)
  rect 4.24x5.2 / inner round 2.337 / far side round 2.337 hole 1.85: 1(8,0)
  silkscreen extent -7.2,-5.6 6,5.6, body extent -9.89,-8.31 10,8.31, height 17.17
KEYSTONE_5011 [mil] "TEST POINT PC MULTIPURPOSE BLK"
  round 110 / inner round 85 / far side round 110 hole 63: 1(0,0)
  silkscreen extent -63,-63 63,63, body extent -62,-62 63,63, height 320
LEDC1005X04NRED,0402, [mm] "Chip LED Body 1.0x0.5mm, IPC Medium Density"
  rect 0.55x0.65 smd: A(0.5,0) K(-0.5,0)
  silkscreen extent -1,-0.38 -1,0.39, body extent -0.53,-0.28 0.52,0.27, height 0.4
LEDC1608X06NGRN,0603, [mm] "LED GRN 0603"
  rect 0.8x0.8 smd: A(0.825,0) K(-0.825,0)
  silkscreen extent -2,-0.5 0.15,0.5, body extent -0.82,-0.4 0.79,0.4, height 0.55
LEDC1608X06NYEL,0603, [mm] "LED YEL 0603"
  rect 0.8x0.8 smd: A(0.825,0) K(-0.825,0)
  silkscreen extent -2,-0.5 0.15,0.5, body extent -0.82,-0.4 0.79,0.4, height 0.55
MOUNT_HOLE_3MM_NOCOPPER [mm] "Mounting hole for M3 screw, unplated"
  round 1 hole 3.4 unplated: 1(0,0)
  Keep-Out Layer circle w1.3: c0,0 r2.35
NEXPERIA_DFN2510_50p250x100x50-10 [mm] "SON, 10-Leads, Body 2.50x1.00mm, Pitch 0.50mm, IPC High Density"
  rect 0.6x0.2 smd: 1(-0.45,1) 2(-0.45,0.5) 3(-0.45,0) 4(-0.45,-0.5) 5(-0.45,-1) 6(0.45,-1) 7(0.45,-0.5) 8(0.45,0) 9(0.45,0.5) 10(0.45,1)
  silkscreen extent -0.6,-1.37 0.25,1.38, body extent -0.6,-1.3 0.6,1.3, height 0.5
NEXPERIA_SOD-323_PESD1LIN [mm] "DIODE GEN PURP"
  rect 0.6x0.6 smd: 1(-1.1,0) 2(1.1,0)
  silkscreen extent -2.1,-0.68 0.9,0.68, body extent -1.25,-0.62 1.25,0.63, height 0.8
ONSEMI_DPAK229P991X238-3N [mm] "D-PAK, 3-Pads, Body 6.21x6.73mm (max), IPC Medium Density"
  rect 3x1.6 smd: 1(-4.4,2.29) 3(-4.4,-2.29)
  rect 6.2x5.8 smd: 4(2.75,0)
  silkscreen extent -4.52,-3.35 -1.55,3.62, body extent -2.45,-3.37 3.77,3.37, height 2.38
QFN50P300X300X100_HS-13N [mm] "QFN, 12-Leads, Body 3.00x3.00mm, Pitch 0.50mm, Thermal Pad 1.43x1.43mm, IPC Medium Density"
  rect 0.7x0.25 smd: 1(-1.45,0.5) 2(-1.45,0) 3(-1.45,-0.5) 7(1.45,-0.5) 8(1.45,0) 9(1.45,0.5)
  rect 0.25x0.7 smd: 4(-0.5,-1.45) 5(0,-1.45) 6(0.5,-1.45) 10(0.5,1.45) 11(0,1.45) 12(-0.5,1.45)
  rect 1.43x1.43 smd: 13(0,0)
  silkscreen extent -2.45,-1.67 1.67,1.68, body extent -1.53,-1.52 1.52,1.53, height 1
RESC1005X40,0402,L [mm] "Chip Resistor, Body 1.0x0.5mm, IPC High Density"
  rect 0.45x0.55 smd: 1(-0.45,0) 2(0.45,0)
  body extent -0.52,-0.27 0.53,0.28, height 0.4
RESC1608X60,0603,L [mm] "Chip Resistor, Body 1.6x0.8mm, IPC High Density"
  rect 0.7x0.9 smd: 1(-0.7,0) 2(0.7,0)
  silkscreen extent -0.05,-0.35 0.05,0.35, body extent -0.85,-0.47 0.85,0.47, height 0.6
RESC3216X70[1206] [mm]
  rect 1.75x1.87 smd: 1(-1.21,0) 2(1.21,0)
  silkscreen extent -2.34,-1.19 2.34,1.19, body extent -1.6,-0.8 1.6,0.8, height 0.89
RESC6534X70[2512] [mm]
  rect 1.3x3.35 smd: 1(-2.975,0) 2(2.975,0)
  silkscreen extent -3.9,-1.9 3.9,1.9, body extent -3.25,-1.65 3.25,1.65, height 0.7
SOD-123 [mil]
  rect 36x48 smd: A(65.35,0) K(-65.35,0)
  silkscreen extent -111,-35 56,35, body extent -73,-31 73,31, height 53
SOD-323 [mil] "DIODE GEN PURP"
  rect 22x27 smd: A(48,0) K(-48,0)
  silkscreen extent -83,-27 35,27, body extent -49,-25 49,25, height 32
SOD-523_130x90x70 [mm] "Diode, SOD-523, 1.2x0.8mm Body, 0.7mm Height"
  rect 0.48x0.4 smd: A(0.66,0) K(-0.66,0)
  silkscreen extent -1.12,-0.4 -1.12,0.4, body extent -0.85,-0.45 0.85,0.45, height 0.7
SOIC127P600X170-8N [mm] "SOIC, 8-Leads, Body 3.90x5mm, Pitch 1.27mm, IPC Medium Density"
  oval 2.2x0.6 smd: 1(-2.4,1.905) 2(-2.4,0.635) 3(-2.4,-0.635) 4(-2.4,-1.905) 5(2.4,-1.905) 6(2.4,-0.635) 7(2.4,0.635) 8(2.4,1.905)
  silkscreen extent -2.52,-2.5 0.9,2.88, body extent -3.02,-2.45 3.02,2.45, height 1.69
SON80P400X100_HS-9N_NOVIA [mm] "SON, 8-Leads, Body 4.00x4.00mm, Pitch 0.80mm, Thermal Pad 3.50x2.49mm, IPC Medium Density"
  rect 0.9x0.3 smd: 1(-2,1.2) 2(-2,0.4) 3(-2,-0.4) 4(-2,-1.2) 5(2,-1.2) 6(2,-0.4) 7(2,0.4) 8(2,1.2)
  rect 2.49x3.5 smd paste-1.245: 9(0,0)
  silkscreen extent -2.65,-2.2 2.2,2.25, body extent -2.05,-2.05 2.05,2.05, height 1
SON127P800X95_HS-9N_no_via [mm] "SON, 8-Leads, Body 6.00x8.00mm, Pitch 1.27mm, Thermal Pad 4.30x3.40mm, IPC Medium Density"
  rect 0.95x0.4 smd: 1(-3.87,1.905) 2(-3.87,0.635) 3(-3.87,-0.635) 4(-3.87,-1.905) 5(3.87,-1.905) 6(3.87,-0.635) 7(3.87,0.635) 8(3.87,1.905)
  rect 3.4x4.3 smd paste-1.7: 9(0,0)
  silkscreen extent -4.75,-3.2 4.2,3.35, body extent -4.05,-3.05 4.05,3.05, height 0.95
SOT23-3#1 [mm]
  rect 0.635x1.2 smd: 1(-0.95,-0.991) 2(0.95,-0.991) 3(0,0.991)
  silkscreen extent -1.52,-0.71 1.52,0.71, body extent -1.45,-1.4 1.45,1.4, height 1.28
SOT23-3#2 [mm]
  rect 1.2x0.635 smd: 1(-0.991,0.95) 2(-0.991,-0.95) 3(0.991,0)
  silkscreen extent -0.71,-1.52 0.71,1.52, body extent -1.4,-1.45 1.4,1.45, height 1.28
SOT23-3B [mm] "Aternate pin config"
  rect 1x1.4 smd: 1(0.95,1) 2(-0.95,1) 3(0,-1)
  silkscreen extent -1.52,-0.71 1.52,0.71, body extent -1.45,-1.4 1.45,1.4, height 1.28
SOT23-6 [mm]
  rect 0.99x0.69 smd: 1(-1.295,0.95)
  oval 0.99x0.69 smd: 2(-1.295,0) 3(-1.295,-0.95) 4(1.295,-0.95) 5(1.295,0) 6(1.295,0.95)
  silkscreen extent -1.61,-1.55 0.87,1.93, body extent -0.8,-1.5 0.8,1.5, height 1.25
SOT230P700X180-4N_ALPHA [mm] "SOT223, 4-Leads, Body 6.50x7.00mm (avg), Pitch 2.30mm, IPC Medium Density"
  rect 2.15x1 smd: D(-2.925,0) G(-2.925,2.3) S(-2.925,-2.3)
  rect 2.15x3.25 smd: D(2.925,0)
  silkscreen extent -3.05,-3.35 1.55,3.47, body extent -1.85,-3.35 1.85,3.35, height 1.8
SOT323_65P200X125x100-GSD [mm] "SOT323, 3-Leads, Body 2.00x2.10mm, Pitch 0.65mm, IPC High Density"
  rect 0.6x0.5 smd: D(0.975,0) G(-0.975,0.65) S(-0.975,-0.65)
  silkscreen extent -0.33,-1.1 0.67,1.1, body extent -1.1,-1.1 1.1,1.1, height 1.1
SOT363 [mm] "Small outline 2.1mm L x 1.25mm W x 1mm H"
  rrect50% 1x0.4 smd: 1(-1.05,0.65) 2(-1.05,0) 3(-1.05,-0.65) 4(1.05,-0.65) 5(1.05,0) 6(1.05,0.65)
  silkscreen extent -1.18,-1.21 1.07,1.21, body extent -1.2,-1.1 1.2,1.1, height 1.1
SOT_23_6 [mm]
  rect 1.1x0.6 smd: 1(-1.35,0.95) 2(-1.35,0) 3(-1.35,-0.95) 4(1.35,-0.95) 5(1.35,0) 6(1.35,0.95)
  silkscreen extent -1.5,-1.73 0.53,1.73, body extent -0.87,-1.5 0.87,1.5, height 1.45
STM_BGA72C40P9X9_441X376X58 [mm] "BGA, 72-Leads, Body 4.41x3.76mmx0.59mm, Pitch 0.40mm"
  round 0.225 smd mask+0.032: A1(-1.6,1.6) A2(-1.2,1.6) A3(-0.8,1.6) A4(-0.4,1.6) A5(0,1.6) A6(0.4,1.6) A7(0.8,1.6) A8(1.2,1.6) A9(1.6,1.6) B1(-1.6,1.2) B2(-1.2,1.2) B3(-0.8,1.2) B4(-0.4,1.2) B5(0,1.2) B6(0.4,1.2) B7(0.8,1.2) B8(1.2,1.2) B9(1.6,1.2) C1(-1.6,0.8) C2(-1.2,0.8) C3(-0.8,0.8) C4(-0.4,0.8) C5(0,0.8) C6(0.4,0.8) C7(0.8,0.8) C8(1.2,0.8) C9(1.6,0.8) D1(-1.6,0.4) D2(-1.2,0.4) D3(-0.8,0.4) D7(0.8,0.4) D8(1.2,0.4) D9(1.6,0.4) E1(-1.6,0) E2(-1.2,0) E3(-0.8,0) E7(0.8,0) E8(1.2,0) E9(1.6,0) F1(-1.6,-0.4) F2(-1.2,-0.4) F3(-0.8,-0.4) F7(0.8,-0.4) F8(1.2,-0.4) F9(1.6,-0.4) G1(-1.6,-0.8) G2(-1.2,-0.8) G3(-0.8,-0.8) G4(-0.4,-0.8) G5(0,-0.8) G6(0.4,-0.8) G7(0.8,-0.8) G8(1.2,-0.8) G9(1.6,-0.8) H1(-1.6,-1.2) H2(-1.2,-1.2) H3(-0.8,-1.2) H4(-0.4,-1.2) H5(0,-1.2) H6(0.4,-1.2) H7(0.8,-1.2) H8(1.2,-1.2) H9(1.6,-1.2) J1(-1.6,-1.6) J2(-1.2,-1.6) J3(-0.8,-1.6) J4(-0.4,-1.6) J5(0,-1.6) J6(0.4,-1.6) J7(0.8,-1.6) J8(1.2,-1.6) J9(1.6,-1.6)
  silkscreen extent -2.54,1.97 -2.29,2.21, body extent -2.2,-1.88 2.2,1.88, height 0.59
STM_PWRFLAT_SON65P200X80_HS-8N [mm] "SON, 6-Leads, Body 2.00x2.00mm, Pitch 0.65mm, Thermal Pad 1.125x1.05mm, IPC Medium Density"
  rect 0.3x0.35 smd: D(-0.875,0) D(-0.875,0.65) D(0.875,0) D(0.875,0.65) G(-0.875,-0.65) S(0.875,-0.65)
  rect 1.125x1.05 smd: D(-0.012,0.3)
  rect 0.95x0.35 smd: S(0.05,-0.65)
  silkscreen extent -1.5,-1.2 1.05,1.25, body extent -1.05,-1.05 1.05,1.05, height 0.81
SULLINS_QPC02SXGN-RC [mm] "jumper (shunt)"
  body extent -2.48,-1.22 2.5,1.23, height 8.3
TAG-TC2030-LEGS [mm] "Tag-Connect TC2030 with legs footprint"
  round 2.375 hole 2.375 unplated mask+0: 0(-2.54,-2.54) 0(-2.54,2.54) 0(0.635,2.54) 0(0.635,-2.54)
  round 0.85 hole 1 unplated mask+0: 0(-2.54,0) 0(2.54,-1.016) 0(2.54,1.016)
  round 0.8 smd paste-0.4: 1(-1.27,-0.635) 2(-1.27,0.635) 3(0,-0.635) 4(0,0.635) 5(1.27,-0.635) 6(1.27,0.635)
  Top Layer keep-out lines w0.1: -0.65,0.5 -0.65,-0.5 ; 0.65,0.5 0.65,-0.5 ; -1.3,0 1.3,0
  Bottom Layer keep-out region: -3.302,3.9 -1.778,3.9 -1.778,4.572 -3.302,4.572
  Bottom Layer keep-out region: -0.127,3.9 1.397,3.9 1.397,4.572 -0.127,4.572
  Bottom Layer keep-out region: -0.127,-4.572 1.397,-4.572 1.397,-3.9 -0.127,-3.9
  Bottom Layer keep-out region: -3.302,-4.572 -1.778,-4.572 -1.778,-3.9 -3.302,-3.9
  silkscreen extent -3.54,-1.8 3.5,1.8
TE_1571300 [mm] "TE Connnectivity SMD R/A momentary switch"
  rect 1.5x3.5 smd: 1(-2,-0.75) 2(2,-0.75)
  round 0.4 hole 0.75 unplated: GUIDE(-4.4,0) GUIDE(4.4,0)
  rect 1.65x2 smd: MNT(-4.775,-2.3) MNT(4.775,-2.3)
  rect 1.65x1.8 smd: MNT(-4.775,1.6) MNT(4.775,1.6)
  silkscreen extent -5.85,-3.2 5.85,2.75, body extent -4.85,-6.7 4.85,1.5, height 8.1
TI-TMP117-WSON [mm]
  rrect33% 0.45x0.3 smd mask+0.07: 1(-0.975,0.65) 2(-0.975,0) 3(-0.975,-0.65) 4(0.975,-0.65) 5(0.975,0) 6(0.975,0.65)
  silkscreen extent -1.7,-1.2 1.1,1.3, body extent -1,-1 1,1, height 0.8
TI_2-X1SON [mm]
  rect 0.6x0.5 smd paste+0 mask+0: 1(-0.5,0) 2(0.5,0)
  silkscreen extent -0.56,-0.6 0.55,0.6, body extent -0.5,-0.3 0.5,0.3, height 0.45
TI_2-X1SON_DFN65P100X60-2L [mm] "DFN, 2-Leads, Body 0.60x1.00mm, Pitch 0.65mm, IPC High Density"
  rect 0.6x0.5 smd paste+0: 1(-0.5,0) 2(0.5,0)
  silkscreen extent -1.01,-0.28 -1.01,0.28, body extent -0.55,-0.35 0.55,0.35, height 0.26
TI_SOT-23-5_95P280X145L [mm] "SOT23, 5-Leads, Body 2.90x2.80mm, Pitch 0.95mm, IPC High Density"
  rrect25% 1.1x0.6 smd mask+0.07: 1(-1.3,0.95) 2(-1.3,0) 3(-1.3,-0.95) 4(1.3,-0.95) 5(1.3,0.95)
  silkscreen extent -1.85,-1.58 0.5,1.58, body extent -1.5,-1.53 1.5,1.53, height 1.45
"TP_SMD_Ø1.0mm NO SILK"#1 [mm]
  round 1 smd paste-5: 1(0,0)
  body extent -0.5,-0.5 0.5,0.5, height 0.03
"TP_SMD_Ø1.0mm NO SILK"#2 [mm]
  round 1 smd paste-5: 1(0,0.2)
  body extent -0.5,-0.5 0.5,0.5, height 0.03
TP_TH078H127P [mil] "30mil Trough Hole Test Point"
  round 50 hole 30 mask+0: 1(0,0)
TSOP65P640X110-14N [mm] "TSOP, 14-Leads, Body 5.00x4.40mm, Pitch 0.65mm, IPC Medium Density"
  rect 1.4x0.45 smd: 1(-2.95,1.95) 2(-2.95,1.3) 3(-2.95,0.65) 4(-2.95,0) 5(-2.95,-0.65) 6(-2.95,-1.3) 7(-2.95,-1.95) 8(2.95,-1.95) 9(2.95,-1.3) 10(2.95,-0.65) 11(2.95,0) 12(2.95,0.65) 13(2.95,1.3) 14(2.95,1.95)
  silkscreen extent -3.07,-2.55 1.85,2.85, body extent -2.25,-2.55 2.25,2.55, height 1.1
VISHAY_SOT563F_SOTFL50P160X60-6N [mm] "SOTFL, 6-Leads, Body 1.60x1.60mm, Pitch 0.50mm, IPC Medium Density"
  rect 0.65x0.3 smd: 1(-0.75,0.5) 2(-0.75,0) 3(-0.75,-0.5) 4(0.75,-0.5) 5(0.75,0) 6(0.75,0.5)
  silkscreen extent -0.87,-0.85 0.05,1.35, body extent -0.63,-0.85 0.63,0.85, height 0.6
